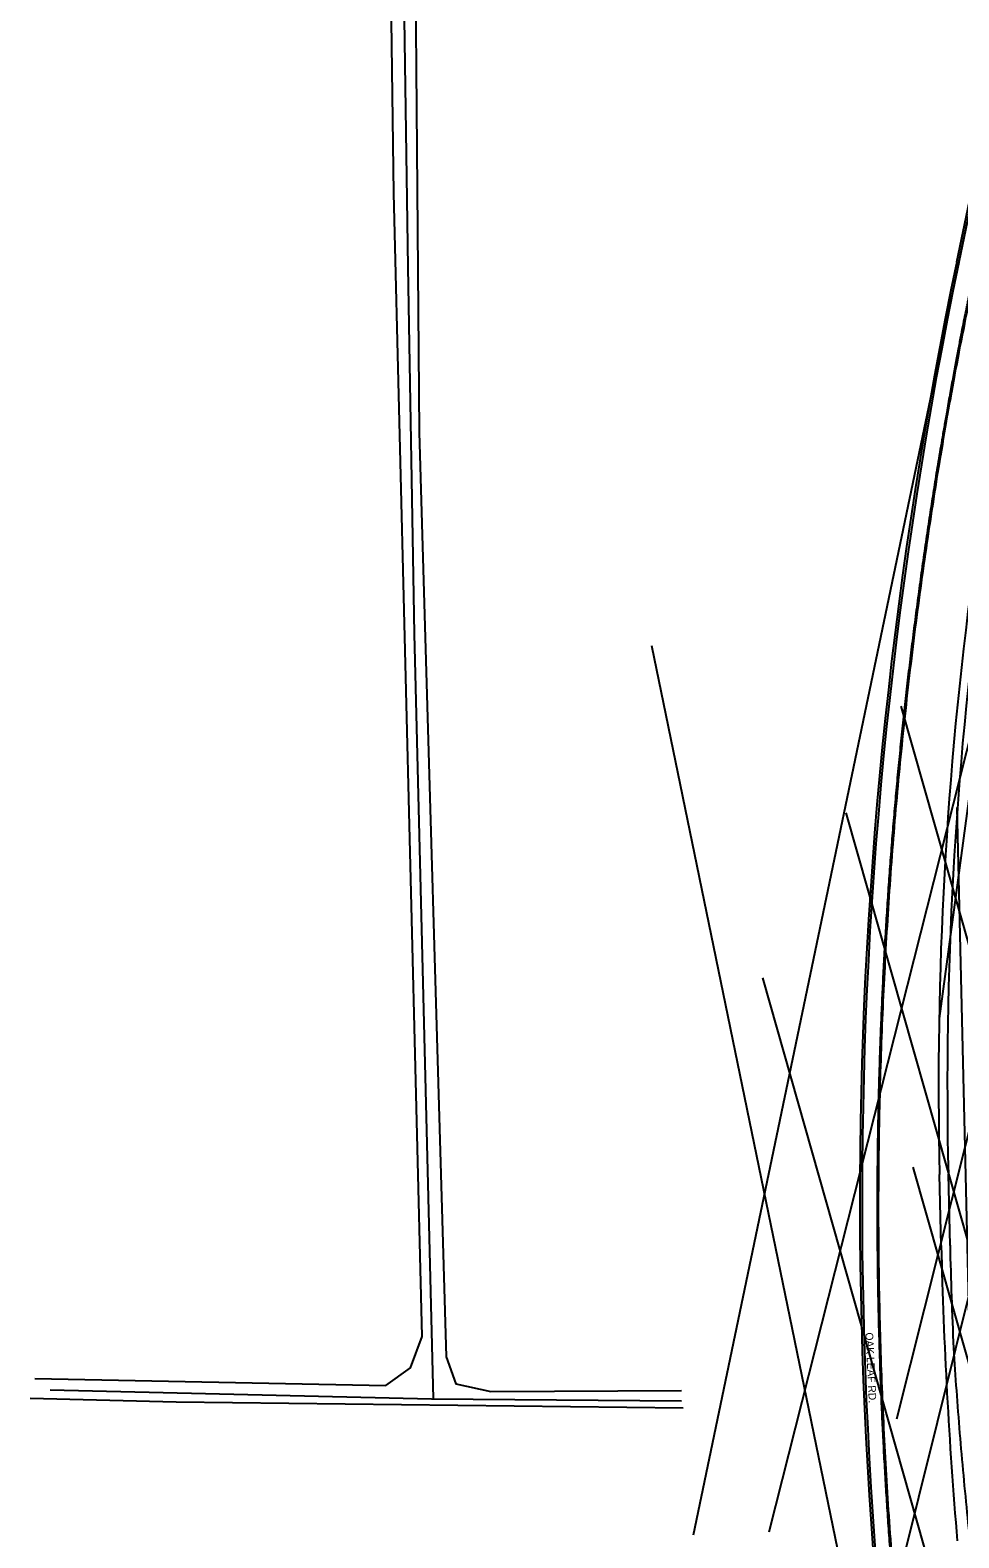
# Model space of a CAD drawing. Extents: x 227157 to 233208, y 434992 to 456232.
# Drawn here: x 227182 to 228031, y 442804 to 444181 of the extents above; entities that cross this region are included whole.
import ezdxf

# ---------------------------------------------------------------- set-up
doc = ezdxf.new("R2010")
doc.units = 0
for name, color, linetype in [('Default', 7, 'Continuous'), ('GE_X_Alignment', 7, 'Continuous'), ('PM_X_Edge_Line', 7, 'Continuous'), ('PV_X_EOP', 7, 'Continuous'), ('SV_X_Text_Name', 7, 'Continuous')]:
    doc.layers.add(name, color=color, linetype=linetype)

msp = doc.modelspace()

# ---------------------------------------------------------------- linework, layer by layer
at = {"layer": 'Default'}
for points, degree in [([(228040.8, 442268.2), (228037.7, 442284.1), (228026.5, 442339), (228009.1, 442439.7), (227997.1, 442519.8), (227985.8, 442605.8), (227976.6, 442690.4), (227969, 442775.7), (227963.1, 442860.9), (227959, 442946.3), (227956.6, 443031.8), (227956, 443117.2), (227957.1, 443202.7), (227960, 443288.1), (227964.6, 443373.5), (227970.9, 443458.7), (227979, 443543.9), (227988.8, 443628.5), (228000.5, 443714.4), (228013, 443794.4), (228030.9, 443895), (228042.4, 443949.9), (228045.6, 443965.8)], 2), ([(228041.7, 442268.4), (228036.2, 442296.2), (228025.2, 442352.1), (228010.8, 442436.2), (227998, 442520.8), (227986.9, 442605.5), (227977.6, 442690.5), (227970, 442775.7), (227964.1, 442860.9), (227960, 442946.3), (227957.6, 443031.8), (227957, 443117.2), (227958.1, 443202.7), (227961, 443288.1), (227965.6, 443373.5), (227971.9, 443458.7), (227980, 443543.8), (227989.8, 443628.7), (228001.4, 443713.3), (228014.6, 443797.8), (228029.5, 443881.9), (228040.9, 443937.7), (228046.6, 443965.6)], 3), ([(228025.6, 442976.9), (228026.5, 442964), (228028.2, 442938.1), (228031.2, 442899.4), (228034.6, 442860.7), (228038.3, 442822.1), (228042.3, 442783.5), (228046.7, 442744.9), (228051.4, 442706.4), (228056.5, 442667.9), (228061.9, 442629.5), (228067.6, 442591.1), (228073.7, 442552.8), (228080.2, 442514.6), (228086.9, 442476.4), (228094.1, 442438.3), (228101.5, 442400.3), (228109.3, 442362.3), (228117.4, 442324.4), (228125.9, 442286.6), (228134.7, 442248.9), (228140.8, 442223.8), (228143.9, 442211.3)], 3)]:
    msp.add_open_spline(points, degree=degree, dxfattribs=at)
at = {"layer": 'GE_X_Alignment'}
for p, q in [((227958.1, 442696), (228945.6, 446675.5)), ((227973.9, 442912.3), (228887.3, 446553.8)), ((227788.2, 442806.3), (228231.6, 444933.5)), ((228012.9, 443278.3), (228230.3, 444895.8)), ((227857.2, 442809.2), (228348.7, 444751.1)), ((227749.9, 443619.1), (228020, 442304.7)), ((229741.1, 437351.7), (227977.9, 443563.5)), ((229633.3, 437464.5), (227927.6, 443466.1)), ((228052, 442484.5), (228029.1, 443470.9)), ((227851.2, 443315.4), (228989, 439305.6)), ((229609.5, 437429.5), (227988.9, 443142.3)), ((227200.5, 442938.8), (227548.8, 442930.7)), ((227548.8, 442930.7), (227777.3, 442928.8))]:
    msp.add_line(p, q, dxfattribs=at)
msp.add_arc((232145.5, 443111.2), 4203.4, 168.2248, 191.6095, dxfattribs=at)
at = {"layer": 'PM_X_Edge_Line'}
for p, q in [((228030.5, 443969), (228231.6, 444933.5)), ((227527.4, 443964.6), (227518.8, 444557.1)), ((227533.4, 443629.6), (227527.4, 443964.6)), ((227550.6, 442930.7), (227533.4, 443629.6)), ((228020.9, 443135.8), (228022.4, 443070.9))]:
    msp.add_line(p, q, dxfattribs=at)
for centre, radius, start, end in [((232145.5, 443111.2), 4203.4, 168.2248, 191.6095), ((231520.5, 443216.8), 3500.5, 172.3433, 181.3271), ((232377.5, 443171.8), 4356.2, 181.3271, 182.5647)]:
    msp.add_arc(centre, radius, start, end, dxfattribs=at)
at = {"layer": 'PV_X_EOP'}
for p, q in [((228028.6, 443969.4), (228105.6, 444338.8)), ((228014.4, 443070.8), (228012.9, 443135.6))]:
    msp.add_line(p, q, dxfattribs=at)
for points in [[(227186.4, 442949.1), (227507, 442942.9), (227529.6, 442959.1), (227540.3, 442987.7), (227514.5, 444032.3), (227499.7, 445113.7), (227491, 445574.8), (227473, 445585.5), (227207.8, 445584.9)], [(227744.7, 445578), (227553.2, 445585.2), (227531, 445579.1), (227520.6, 445561.2), (227531.8, 444516), (227537.7, 443813.8), (227562.1, 442969.1), (227570.9, 442944.3), (227603.1, 442937.5), (227777.2, 442938.3)], [(227778.8, 442922.1), (227315.6, 442927.7), (227182.2, 442930.9)]]:
    msp.add_lwpolyline(points, dxfattribs=at)
for centre, radius, start, end in [((232145.5, 443111.2), 4205.4, 168.2248, 191.2092), ((231520.5, 443216.8), 3508.5, 172.3433, 181.3271), ((232377.5, 443171.8), 4364.2, 181.3271, 184.8752)]:
    msp.add_arc(centre, radius, start, end, dxfattribs=at)

# ---------------------------------------------------------------- texts
at = {"layer": 'SV_X_Text_Name'}
msp.add_text('OAK LEAF RD.', height=7, rotation=272.786, dxfattribs=at).set_placement((227945.2, 442991.1))

doc.saveas('drawing.dxf')
